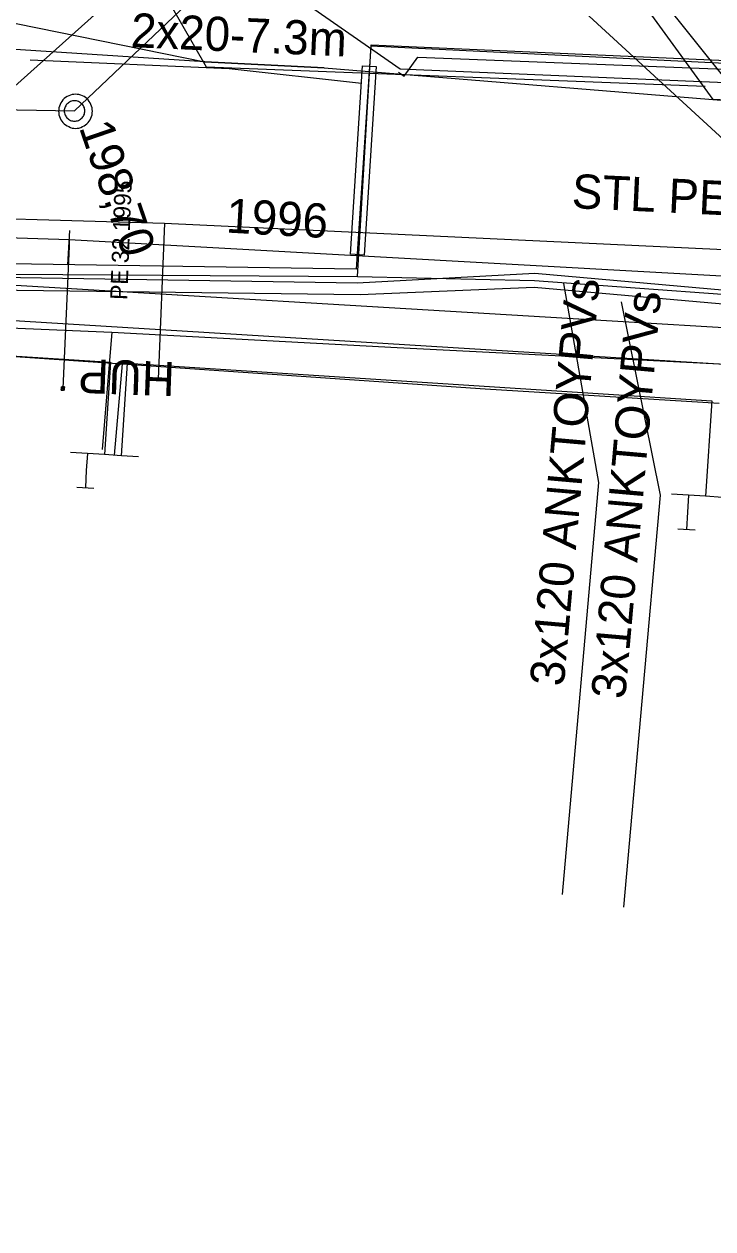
# Model space of a CAD drawing. Extents: x -746464 to -745690, y -1051581 to -1049993.
# Drawn here: x -746338.99 to -746318.83, y -1051059.52 to -1051024.28 of the extents above; entities that cross this region are included whole.
import ezdxf

# ---------------------------------------------------------------- set-up
doc = ezdxf.new("R2010")
doc.units = 0
for name, color, linetype in [('04_CETIN_neprovozovane', 7, 'Continuous'), ('04_CETIN_sdelovaci_podzem', 7, 'Continuous'), ('45_Eltodo_sdelovaci_kabel_ovladaci', 7, 'Continuous'), ('45_Eltodo_vedeni_NN_zemni', 7, 'Continuous'), ('48_Prazs_plynarenska_STL', 7, 'Continuous'), ('48_Prazs_plynarenska_STL_popisy', 7, 'Continuous'), ('51_PVaK_kanal_jednotna_neoverena poloha_pripojka', 7, 'Continuous'), ('51_PVaK_kanal_jednotna_overena poloha_rad', 7, 'Continuous'), ('51_PVaK_kanal_objekty', 7, 'Continuous'), ('51_PVaK_kanal_popisy', 7, 'Continuous'), ('51_PVaK_vodovod_chranicky_objekty', 7, 'Continuous'), ('51_PVaK_vodovod_overena poloha_pripojka', 7, 'Continuous'), ('51_PVaK_vodovod_overena poloha_rad', 7, 'Continuous'), ('51_PVaK_vodovod_popisy', 7, 'Continuous'), ('55_PREdi_chranicky', 7, 'Continuous'), ('55_PREdi_NN', 7, 'Continuous'), ('55_PREdi_NN_pripojovaci_misto', 7, 'Continuous'), ('55_PREdi_stavby_popisy', 7, 'Continuous'), ('55_PREdi_VN', 7, 'Continuous'), ('55_PREdi_VN_popisy', 7, 'Continuous'), ('55_PREdi_ZRUSENE_elektro', 7, 'Continuous')]:
    doc.layers.add(name, color=color, linetype=linetype)

msp = doc.modelspace()

# ---------------------------------------------------------------- linework, layer by layer
at = {"layer": '04_CETIN_neprovozovane'}
msp.add_lwpolyline([(-746333.7, -1051025.38), (-746350.34, -1051024.3)], dxfattribs=at)
at = {"layer": '04_CETIN_sdelovaci_podzem'}
for points in [[(-746351.52, -1051021.76), (-746333.7, -1051025.38), (-746330.21, -1051025.56), (-746316.79, -1051026.65)], [(-746330.21, -1051025.56), (-746333.7, -1051025.38)], [(-746357.76, -1051032.24), (-746342.4, -1051033.04), (-746336.42, -1051033.29)], [(-746336.42, -1051033.29), (-746336.7, -1051036.72)], [(-746336.42, -1051033.29), (-746328.07, -1051033.74), (-746315.95, -1051034.35), (-746310.81, -1051034.66)]]:
    msp.add_lwpolyline(points, dxfattribs=at)
at = {"layer": '45_Eltodo_sdelovaci_kabel_ovladaci'}
msp.add_lwpolyline([(-746458.107, -1051040.596), (-746452.238, -1051038.914), (-746452.533, -1051024.817), (-746441.647, -1051021.908), (-746427.884, -1051017.81), (-746425.007, -1051017.632), (-746423.494, -1051014.247), (-746406.379, -1051019.532), (-746393.969, -1051021.364), (-746377.076, -1051023.037), (-746371.357, -1051023.39), (-746350.592, -1051020.748), (-746343.378, -1051018.106), (-746337.043, -1051014.584), (-746330.796, -1051018.194), (-746332.907, -1051022.157), (-746327.98, -1051025.591), (-746302.693, -1051026.653), (-746280.345, -1051027.533), (-746279.938, -1051027.788)], dxfattribs=at)
at = {"layer": '45_Eltodo_vedeni_NN_zemni'}
msp.add_lwpolyline([(-746328.031, -1051025.689), (-746327.867, -1051025.803), (-746327.468, -1051025.244), (-746302.762, -1051026.216), (-746302.786, -1051026.801), (-746302.586, -1051026.809)], dxfattribs=at)
at = {"layer": '48_Prazs_plynarenska_STL'}
for points in [[(-746343.01, -1051029.87), (-746342.98, -1051029.42), (-746332.94, -1051020.43), (-746328.67, -1051016.61), (-746327.91, -1051017.6), (-746325.69, -1051015.95), (-746319.84, -1051009.87), (-746318.39, -1051008.02), (-746319.01, -1051007.63), (-746317.08, -1051005.01), (-746313.738, -1051002.152), (-746308.46, -1050997.64), (-746302.4, -1050994.1), (-746287, -1050984.1), (-746276.62, -1050976.16), (-746273.63, -1050976.714)], [(-746343.01, -1051029.87), (-746334.88, -1051030.1), (-746316.85, -1051030.95), (-746315.163, -1051031.028), (-746305.09, -1051031.5), (-746303.239, -1051031.589)], [(-746334.88, -1051030.1), (-746335.058, -1051034.668)]]:
    msp.add_lwpolyline(points, dxfattribs=at)
at = {"layer": '51_PVaK_kanal_jednotna_neoverena poloha_pripojka'}
msp.add_line((-746308.49, -1051036.89), (-746328.62, -1051018.364), dxfattribs=at)
at = {"layer": '51_PVaK_kanal_jednotna_overena poloha_rad'}
for points in [[(-746337.51, -1051026.82), (-746328.62, -1051018.364), (-746307.39, -1050998.17)], [(-746388.25, -1051025.95), (-746340.31, -1051026.772), (-746337.51, -1051026.82)]]:
    msp.add_lwpolyline(points, dxfattribs=at)
at = {"layer": '51_PVaK_kanal_objekty'}
for points in [[(-746336.98, -1051026.83), (-746336.99, -1051026.78), (-746336.99, -1051026.73), (-746337.01, -1051026.68), (-746337.03, -1051026.63), (-746337.05, -1051026.58), (-746337.08, -1051026.54), (-746337.11, -1051026.5), (-746337.15, -1051026.46), (-746337.19, -1051026.43), (-746337.23, -1051026.4), (-746337.28, -1051026.38), (-746337.33, -1051026.36), (-746337.38, -1051026.34), (-746337.43, -1051026.34), (-746337.48, -1051026.33), (-746337.53, -1051026.34), (-746337.58, -1051026.34), (-746337.63, -1051026.36), (-746337.68, -1051026.38), (-746337.73, -1051026.4), (-746337.77, -1051026.43), (-746337.81, -1051026.46), (-746337.85, -1051026.5), (-746337.88, -1051026.54), (-746337.91, -1051026.58), (-746337.93, -1051026.63), (-746337.95, -1051026.68), (-746337.97, -1051026.73), (-746337.97, -1051026.78), (-746337.98, -1051026.83), (-746337.97, -1051026.88), (-746337.97, -1051026.93), (-746337.95, -1051026.98), (-746337.93, -1051027.03), (-746337.91, -1051027.08), (-746337.88, -1051027.12), (-746337.85, -1051027.16), (-746337.81, -1051027.2), (-746337.77, -1051027.23), (-746337.73, -1051027.26), (-746337.68, -1051027.28), (-746337.63, -1051027.3), (-746337.58, -1051027.32), (-746337.53, -1051027.32), (-746337.48, -1051027.33), (-746337.43, -1051027.32), (-746337.38, -1051027.32), (-746337.33, -1051027.3), (-746337.28, -1051027.28), (-746337.23, -1051027.26), (-746337.19, -1051027.23), (-746337.15, -1051027.2), (-746337.11, -1051027.16), (-746337.08, -1051027.12), (-746337.05, -1051027.08), (-746337.03, -1051027.03), (-746337.01, -1051026.98), (-746336.99, -1051026.93), (-746336.99, -1051026.88), (-746336.98, -1051026.83)], [(-746337.21, -1051026.82), (-746337.21, -1051026.79), (-746337.216, -1051026.76), (-746337.222, -1051026.73), (-746337.234, -1051026.7), (-746337.252, -1051026.67), (-746337.27, -1051026.646), (-746337.288, -1051026.622), (-746337.312, -1051026.598), (-746337.336, -1051026.58), (-746337.36, -1051026.562), (-746337.39, -1051026.544), (-746337.42, -1051026.532), (-746337.45, -1051026.526), (-746337.48, -1051026.52), (-746337.51, -1051026.52), (-746337.54, -1051026.52), (-746337.57, -1051026.526), (-746337.6, -1051026.532), (-746337.63, -1051026.544), (-746337.66, -1051026.562), (-746337.684, -1051026.58), (-746337.708, -1051026.598), (-746337.732, -1051026.622), (-746337.75, -1051026.646), (-746337.768, -1051026.67), (-746337.786, -1051026.7), (-746337.798, -1051026.73), (-746337.804, -1051026.76), (-746337.81, -1051026.79), (-746337.81, -1051026.82), (-746337.81, -1051026.85), (-746337.804, -1051026.88), (-746337.798, -1051026.91), (-746337.786, -1051026.94), (-746337.768, -1051026.97), (-746337.75, -1051026.994), (-746337.732, -1051027.018), (-746337.708, -1051027.042), (-746337.684, -1051027.06), (-746337.66, -1051027.078), (-746337.63, -1051027.096), (-746337.6, -1051027.108), (-746337.57, -1051027.114), (-746337.54, -1051027.12), (-746337.51, -1051027.12), (-746337.48, -1051027.12), (-746337.45, -1051027.114), (-746337.42, -1051027.108), (-746337.39, -1051027.096), (-746337.36, -1051027.078), (-746337.336, -1051027.06), (-746337.312, -1051027.042), (-746337.288, -1051027.018), (-746337.27, -1051026.994), (-746337.252, -1051026.97), (-746337.234, -1051026.94), (-746337.222, -1051026.91), (-746337.216, -1051026.88), (-746337.21, -1051026.85), (-746337.21, -1051026.82)]]:
    msp.add_lwpolyline(points, dxfattribs=at)
at = {"layer": '51_PVaK_vodovod_chranicky_objekty'}
for p, q in [((-746337.701, -1051031.32), (-746337.644, -1051030.32)), ((-746337.903, -1051034.988), (-746337.799, -1051034.892)), ((-746337.903, -1051034.988), (-746337.902, -1051034.968)), ((-746337.903, -1051034.988), (-746337.883, -1051034.989)), ((-746337.899, -1051034.888), (-746337.9, -1051034.908)), ((-746337.803, -1051034.992), (-746337.899, -1051034.888)), ((-746337.899, -1051034.888), (-746337.879, -1051034.889)), ((-746337.803, -1051034.992), (-746337.823, -1051034.991)), ((-746337.799, -1051034.892), (-746337.819, -1051034.891)), ((-746337.803, -1051034.992), (-746337.802, -1051034.972)), ((-746337.799, -1051034.892), (-746337.8, -1051034.912))]:
    msp.add_line(p, q, dxfattribs=at)
msp.add_lwpolyline([(-746337.849, -1051034.89), (-746337.854, -1051034.89), (-746337.859, -1051034.89), (-746337.864, -1051034.891), (-746337.869, -1051034.893), (-746337.874, -1051034.896), (-746337.878, -1051034.899), (-746337.882, -1051034.901), (-746337.886, -1051034.905), (-746337.89, -1051034.909), (-746337.893, -1051034.913), (-746337.896, -1051034.918), (-746337.898, -1051034.923), (-746337.899, -1051034.928), (-746337.901, -1051034.933), (-746337.901, -1051034.938), (-746337.901, -1051034.943), (-746337.9, -1051034.948), (-746337.899, -1051034.953), (-746337.898, -1051034.958), (-746337.895, -1051034.963), (-746337.892, -1051034.967), (-746337.889, -1051034.971), (-746337.885, -1051034.975), (-746337.882, -1051034.979), (-746337.878, -1051034.982), (-746337.873, -1051034.985), (-746337.868, -1051034.987), (-746337.863, -1051034.988), (-746337.858, -1051034.99), (-746337.853, -1051034.99), (-746337.848, -1051034.99), (-746337.843, -1051034.989), (-746337.838, -1051034.988), (-746337.833, -1051034.987), (-746337.828, -1051034.984), (-746337.824, -1051034.981), (-746337.819, -1051034.978), (-746337.815, -1051034.974), (-746337.812, -1051034.971), (-746337.809, -1051034.967), (-746337.806, -1051034.962), (-746337.804, -1051034.957), (-746337.802, -1051034.952), (-746337.801, -1051034.947), (-746337.801, -1051034.942), (-746337.801, -1051034.937), (-746337.801, -1051034.932), (-746337.802, -1051034.927), (-746337.804, -1051034.922), (-746337.807, -1051034.917), (-746337.81, -1051034.913), (-746337.812, -1051034.908), (-746337.816, -1051034.904), (-746337.82, -1051034.901), (-746337.824, -1051034.898), (-746337.829, -1051034.895), (-746337.834, -1051034.893), (-746337.839, -1051034.891), (-746337.844, -1051034.89), (-746337.849, -1051034.89)], dxfattribs=at)
at = {"layer": '51_PVaK_vodovod_overena poloha_pripojka'}
for p, q in [((-746337.67, -1051030.59), (-746337.67, -1051030.78)), ((-746337.67, -1051030.78), (-746337.85, -1051034.94))]:
    msp.add_line(p, q, dxfattribs=at)
at = {"layer": '51_PVaK_vodovod_overena poloha_rad'}
msp.add_lwpolyline([(-746309.67, -1051031.81), (-746316.12, -1051031.79), (-746337.67, -1051030.59), (-746343.17, -1051030.42), (-746362.87, -1051029.02), (-746375.92, -1051028.87), (-746376.91, -1051028.85), (-746393.26, -1051027.88)], dxfattribs=at)
at = {"layer": '55_PREdi_chranicky'}
msp.add_lwpolyline([(-746329.438, -1051031.01), (-746329.082, -1051025.498), (-746328.682, -1051025.524), (-746329.038, -1051031.036), (-746329.438, -1051031.01)], close=True, dxfattribs=at)
at = {"layer": '55_PREdi_NN'}
for points in [[(-746317.039, -1051026.572), (-746318.823, -1051026.486), (-746327.536, -1051014.504), (-746311.76, -1051000.614), (-746293.31, -1050989.459), (-746270.27, -1050970.787), (-746268.96, -1050925.936), (-746274.791, -1050900.587), (-746280.96, -1050896.444), (-746281.902, -1050889.994), (-746278.512, -1050882.884), (-746280.08, -1050871.671), (-746281.012, -1050871.801)], [(-746298.351, -1051026.8), (-746317.519, -1051026.231), (-746318.234, -1051026.166), (-746328.24, -1051013.684)], [(-746391.185, -1051051.583), (-746390.216, -1051047.371), (-746382.305, -1051038.755), (-746363.137, -1051039.555), (-746362.619, -1051031.221), (-746341.851, -1051031.762), (-746309.546, -1051033.692), (-746300.786, -1051027.36), (-746317.039, -1051026.572)], [(-746280.37, -1051027.926), (-746299.562, -1051027.525), (-746308.133, -1051033.975), (-746308.18, -1051034.869), (-746341.992, -1051032.798), (-746361.536, -1051032.304), (-746362.148, -1051040.637), (-746382.069, -1051039.743), (-746389.266, -1051047.593), (-746391.3, -1051056.458), (-746392.161, -1051056.537)], [(-746361.19, -1051041.571), (-746360.684, -1051036.065), (-746360.485, -1051033.242), (-746342.093, -1051033.806), (-746336.112, -1051034.22)], [(-746349.083, -1051049.747), (-746349.531, -1051049.413), (-746349.197, -1051048.97), (-746360.971, -1051040.355), (-746360.547, -1051033.175), (-746342.093, -1051033.806), (-746336.459, -1051034.169), (-746336.633, -1051036.873)], [(-746336.112, -1051034.22), (-746336.346, -1051036.889)], [(-746336.135, -1051036.905), (-746335.96, -1051034.201), (-746318.865, -1051035.303), (-746319.045, -1051038.094)], [(-746336.112, -1051034.22), (-746325.492, -1051034.954), (-746318.644, -1051035.365)], [(-746335.636, -1051036.937), (-746336.135, -1051036.905), (-746336.633, -1051036.873), (-746337.132, -1051036.841), (-746337.631, -1051036.809)], [(-746337.132, -1051036.841), (-746337.165, -1051037.34)], [(-746318.048, -1051038.158), (-746318.547, -1051038.126), (-746319.045, -1051038.094), (-746319.544, -1051038.062), (-746320.043, -1051038.03)], [(-746319.544, -1051038.062), (-746319.577, -1051038.561)]]:
    msp.add_lwpolyline(points, dxfattribs=at)
at = {"layer": '55_PREdi_NN_pripojovaci_misto'}
for p, q in [((-746337.165, -1051037.34), (-746337.191, -1051037.839)), ((-746337.441, -1051037.826), (-746336.942, -1051037.852)), ((-746319.577, -1051038.561), (-746319.603, -1051039.06)), ((-746319.853, -1051039.047), (-746319.354, -1051039.073))]:
    msp.add_line(p, q, dxfattribs=at)
at = {"layer": '55_PREdi_stavby_popisy'}
msp.add_lwpolyline([(-746338.811, -1051025.327), (-746332.983, -1051025.58), (-746329.114, -1051026.006)], dxfattribs=at)
at = {"layer": '55_PREdi_VN'}
for points in [[(-746287.073, -1051027.37), (-746298.364, -1051026.818), (-746307.279, -1051033.065), (-746324.041, -1051031.578), (-746329.242, -1051031.86), (-746350.796, -1051031.518), (-746366.665, -1051032.16), (-746384.616, -1051031.987), (-746387.613, -1051045.146), (-746389.289, -1051050.68), (-746391.174, -1051055.991), (-746397.017, -1051056.857), (-746397.448, -1051055.909), (-746397.565, -1051055.025), (-746397.231, -1051051.998)], [(-746329.228, -1051031.663), (-746324.05, -1051031.778), (-746306.907, -1051033.025), (-746297.96, -1051026.675)], [(-746388.906, -1051050.796), (-746387.226, -1051045.249), (-746384.298, -1051032.39), (-746366.659, -1051032.56), (-746350.78, -1051031.918), (-746329.153, -1051032.19), (-746324.06, -1051031.978), (-746307.161, -1051033.471), (-746298.245, -1051027.223), (-746290.453, -1051027.606)], [(-746391.086, -1051056.19), (-746389.289, -1051050.68), (-746387.613, -1051045.146), (-746384.616, -1051031.987), (-746366.665, -1051032.16), (-746350.796, -1051031.518), (-746329.228, -1051031.663)]]:
    msp.add_lwpolyline(points, dxfattribs=at)
at = {"layer": '55_PREdi_VN_popisy'}
for points in [[(-746323.23, -1051049.744), (-746322.164, -1051037.687), (-746323.189, -1051031.864)], [(-746321.436, -1051050.117), (-746320.367, -1051038.059), (-746321.507, -1051032.401)]]:
    msp.add_lwpolyline(points, dxfattribs=at)
at = {"layer": '55_PREdi_ZRUSENE_elektro'}
for points in [[(-746338.669, -1051016.78), (-746333.659, -1051025.534), (-746319.053, -1051026.098)], [(-746278.152, -1051020.538), (-746272.98, -1051020.897), (-746273.167, -1051027.65), (-746328.844, -1051024.925), (-746329.266, -1051031.449), (-746350.812, -1051031.118), (-746366.671, -1051031.76), (-746384.934, -1051031.584), (-746388, -1051045.043), (-746389.672, -1051050.564), (-746391.617, -1051056.146), (-746391.114, -1051057.599), (-746392.877, -1051068.295), (-746395.244, -1051075.498)], [(-746329.228, -1051031.663), (-746328.827, -1051024.883), (-746318.431, -1051025.344), (-746297.96, -1051026.675)]]:
    msp.add_lwpolyline(points, dxfattribs=at)

# ---------------------------------------------------------------- texts
at = {"layer": '48_Prazs_plynarenska_STL_popisy'}
for s, height, rotation, p in [('STL PE 160 1995', 1, 357.3009, (-746322.975, -1051029.66)), ('PE 32 1995', 0.5, 87.7685, (-746335.969, -1051032.357)), ('HUP', 1, 178, (-746334.558, -1051034.168))]:
    msp.add_text(s, height=height, rotation=rotation, dxfattribs=at).set_placement(p)
at = {"layer": '51_PVaK_kanal_popisy'}
msp.add_text('198,70', height=1, rotation=288.984, dxfattribs=at).set_placement((-746337.387, -1051027.298))
at = {"layer": '51_PVaK_vodovod_popisy'}
msp.add_text('1996', height=1, rotation=356.8138, dxfattribs=at).set_placement((-746333.091, -1051030.376))
at = {"layer": '55_PREdi_stavby_popisy'}
msp.add_text('2x20-7.3m', height=1, rotation=357.5051, dxfattribs=at).set_placement((-746335.875, -1051024.954))
at = {"layer": '55_PREdi_VN_popisy'}
for rotation, p in [(84.9504, (-746323.195, -1051043.671)), (84.9308, (-746321.4, -1051044.044))]:
    msp.add_text('3x120 ANKTOYPVs', height=1, rotation=rotation, dxfattribs=at).set_placement(p)

doc.saveas('drawing.dxf')
